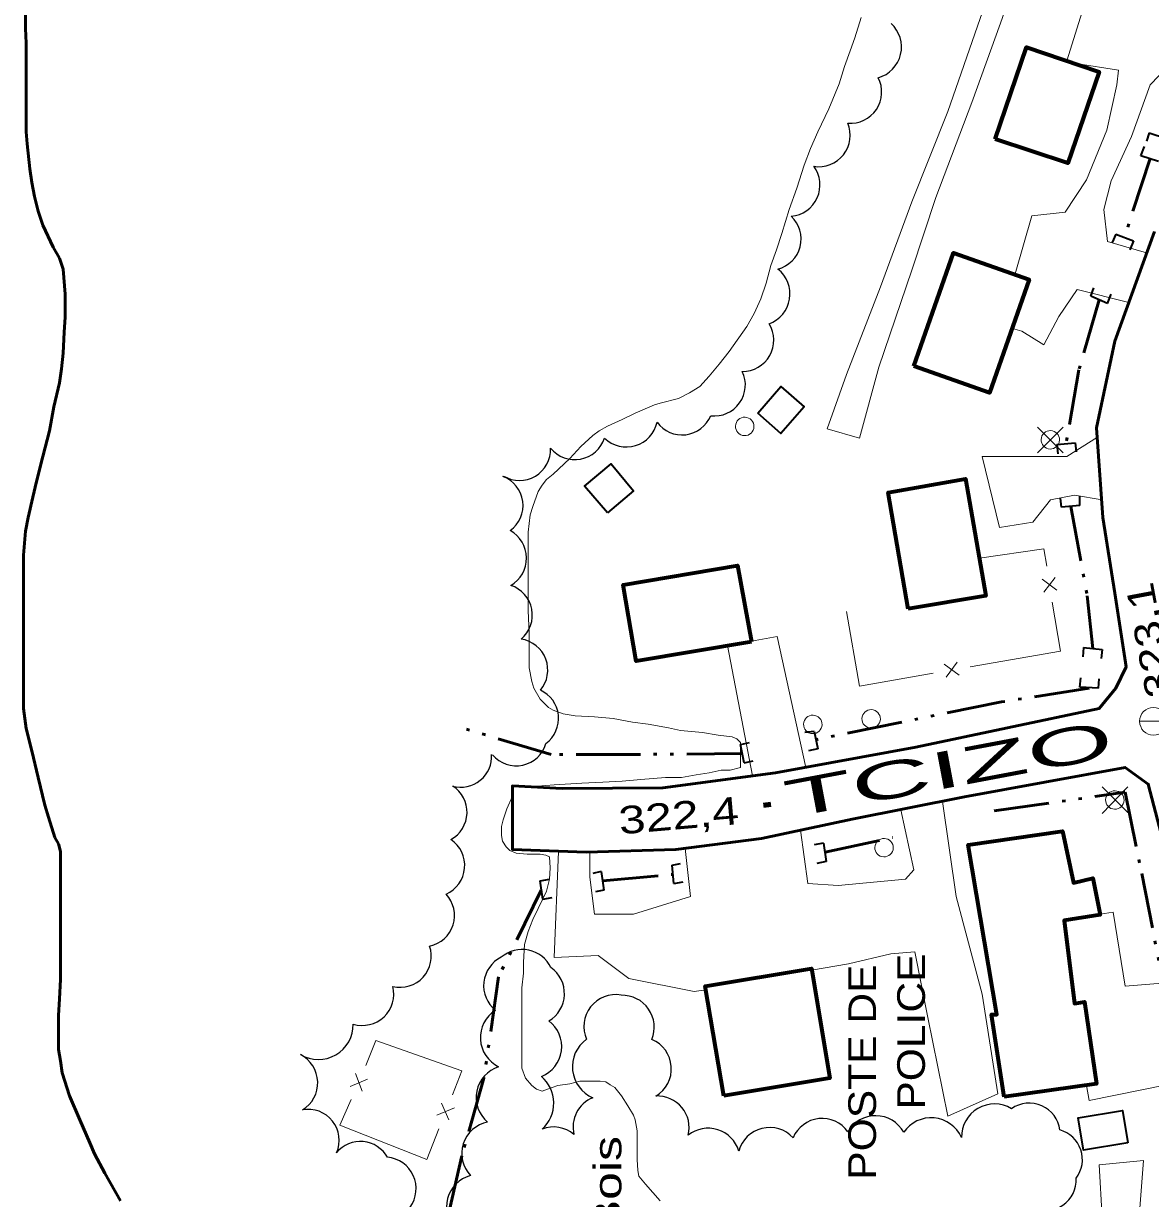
# Model space of a CAD drawing. Extents: x 240591 to 242335, y 5323482 to 5326937.
# Drawn here: x 240782 to 240904.2, y 5324661.9 to 5324789.3 of the extents above; entities that cross this region are included whole.
import ezdxf
from ezdxf.enums import TextEntityAlignment as Align

# ---------------------------------------------------------------- set-up
doc = ezdxf.new("R2010")
doc.units = 0
doc.header["$LTSCALE"] = 1.2
doc.linetypes.add('DASH_DOUBLE_DOT', pattern=[9.2, 5, -1.2, 0.3, -1.2, 0.3, -1.2])
doc.linetypes.add('LONG_DASHED', pattern=[7.5, 6, -1.5])
for name, color, linetype, lineweight in [('1', 7, 'Continuous', 53), ('19', 7, 'Continuous', 13), ('2', 7, 'Continuous', 13), ('21', 7, 'Continuous', 53), ('26', 7, 'Continuous', 35), ('3', 7, 'Continuous', 140), ('31', 7, 'Continuous', 70), ('36', 7, 'Continuous', 13), ('37', 7, 'Continuous', 13), ('4', 7, 'DASH_DOUBLE_DOT', 53), ('44', 7, 'Continuous', 25)]:
    doc.layers.add(name, color=color, linetype=linetype, lineweight=lineweight)

msp = doc.modelspace()

# ---------------------------------------------------------------- linework, layer by layer
at = {"layer": '1', "linetype": 'LONG_DASHED'}
msp.add_lwpolyline([(240792.5, 5324661.6), (240790.8, 5324664.6), (240789.7, 5324666.7), (240789.2, 5324667.9), (240788.1, 5324670.4), (240787, 5324673), (240786.2, 5324675.5), (240786, 5324676.8), (240785.8, 5324678), (240785.8, 5324679.1), (240785.8, 5324681.7), (240785.9, 5324683.5), (240786, 5324685.6), (240786, 5324688.1), (240786, 5324690.8), (240786, 5324693.6), (240786, 5324696.8), (240786, 5324699.5), (240785.8, 5324700.3), (240785.4, 5324701), (240784.7, 5324703.2), (240784.3, 5324704.5), (240783.6, 5324707.5), (240782.9, 5324710.4), (240782.3, 5324712.8), (240782, 5324715), (240782, 5324716.1), (240782, 5324719.8), (240782, 5324723.1), (240782, 5324726.3), (240782, 5324729.1), (240782, 5324731.6), (240782.2, 5324734.2), (240782.5, 5324735.7), (240783, 5324737.9), (240783.4, 5324739.6), (240784.1, 5324742.3), (240784.8, 5324745.1), (240785.3, 5324747.7), (240785.9, 5324750.3), (240786.1, 5324751.8), (240786.3, 5324753.5), (240786.4, 5324755.8), (240786.5, 5324757.4), (240786.5, 5324759.9), (240786.3, 5324762.6), (240785.9, 5324763.8), (240785.2, 5324765), (240784.1, 5324767.4), (240783.6, 5324768.9), (240783.2, 5324770.5), (240782.9, 5324772), (240782.7, 5324773.5), (240782.4, 5324776.2), (240782.3, 5324777.5), (240782.3, 5324779.8), (240782.3, 5324783.8), (240782.3, 5324787.1), (240782.2, 5324788.7), (240782.2, 5324791.6)], dxfattribs=at)
at = {"layer": '19'}
msp.add_line((240861, 5324707.7), (240858.3, 5324721.8), dxfattribs=at)
for points in [[(240905.5, 5324848.2), (240901.4, 5324836.4), (240898.2, 5324827.8), (240894.3, 5324814.9), (240890.3, 5324803), (240885.7, 5324789.8), (240882.2, 5324779.7), (240878.3, 5324769.9), (240874.9, 5324760.7), (240871.2, 5324751.2), (240869.1, 5324745.3), (240872.6, 5324744.3), (240874.7, 5324752), (240878.3, 5324762.5), (240880.9, 5324770.4), (240884.8, 5324780.7), (240887.9, 5324789.3), (240890.9, 5324797.9), (240894.2, 5324806.8), (240897.9, 5324817.2), (240900.9, 5324827.7), (240904.5, 5324836.1)], [(240895.1, 5324785.2), (240897.3, 5324792.3), (240902.9, 5324790.7), (240904.8, 5324794.1), (240907.1, 5324800.2), (240910.3, 5324809.3), (240903.8, 5324811.6), (240906, 5324817), (240912, 5324816), (240913.6, 5324817.7), (240916, 5324825.2), (240917.2, 5324831), (240909.6, 5324833.5)], [(240910.6, 5324783.9), (240907, 5324785.6), (240904.1, 5324782.6), (240902.1, 5324777), (240899.9, 5324772.2), (240899.1, 5324769.1), (240899.5, 5324765.6), (240902.6, 5324764.7), (240903.7, 5324764.4)], [(240889.5, 5324762.1), (240891.3, 5324768.4), (240894.9, 5324768.8), (240897.2, 5324772.3), (240899.4, 5324777.7), (240900.5, 5324782.6), (240900.7, 5324784.2), (240896.1, 5324784.9)], [(240901.8, 5324759), (240896.2, 5324760.4), (240894.2, 5324757.5), (240892.6, 5324754.4), (240890.2, 5324755.9), (240889.2, 5324756.2)], [(240898.4, 5324744.4), (240895.1, 5324742.3), (240885.9, 5324742.3), (240887.8, 5324734.6), (240891.4, 5324735.2), (240893.3, 5324737.6), (240895.9, 5324738.1), (240898.9, 5324737.6)], [(240860.9, 5324722.3), (240863.7, 5324722.8), (240866.8, 5324708.6)], [(240877.1, 5324704), (240878.5, 5324697.5), (240877.6, 5324696.5), (240870.3, 5324695.8), (240867, 5324696), (240866.2, 5324701.8)], [(240867.4, 5324686.6), (240871.4, 5324687.3), (240876, 5324688.4), (240878.6, 5324688.6), (240880, 5324681.5), (240882.2, 5324670.8), (240887.6, 5324673.2), (240885.9, 5324684), (240883.1, 5324694.6), (240881.6, 5324704.9)], [(240840, 5324699.5), (240839.5, 5324688), (240844.3, 5324688.2), (240847.6, 5324685.7), (240854.7, 5324684.3), (240856, 5324684.5)], [(240853.7, 5324699.8), (240854.3, 5324694.6), (240848.1, 5324692.7), (240843.9, 5324692.7), (240843.4, 5324696.7), (240843.4, 5324699.4)], [(240898.7, 5324692.7), (240900.1, 5324692.9), (240901.4, 5324684.9), (240905.4, 5324685.2), (240908.2, 5324685.9)], [(240910.4, 5324675), (240905.9, 5324674.2), (240897.5, 5324672.5), (240897.2, 5324674.1)], [(240898.3, 5324655.2), (240898.9, 5324659.8), (240898.6, 5324665.5), (240903.4, 5324666), (240902.9, 5324659.4), (240903.2, 5324656.4)]]:
    msp.add_lwpolyline(points, dxfattribs=at)
at = {"layer": '2'}
msp.add_line((240838.6, 5324699.1), (240838, 5324699.2), dxfattribs=at)
for points in [[(240854.4, 5324712.5), (240853.2, 5324712.6), (240851.9, 5324712.9), (240849.7, 5324713.3), (240848, 5324713.5), (240845.9, 5324713.9), (240843.9, 5324714.1), (240841.8, 5324714.2), (240840.5, 5324714.4), (240839.4, 5324714.8), (240838.9, 5324715.1), (240838, 5324716), (240837.3, 5324717.2), (240837.1, 5324717.9), (240836.8, 5324719.4), (240836.8, 5324720.3), (240836.8, 5324723.1), (240836.7, 5324725.6), (240836.7, 5324728.4), (240836.7, 5324731.2), (240836.7, 5324734.1), (240836.9, 5324736), (240837.2, 5324736.9), (240837.8, 5324738.5), (240838.2, 5324739.2), (240838.7, 5324739.8), (240839.4, 5324740.4), (240841.2, 5324742.1), (240842.4, 5324743.4), (240843.7, 5324744.6), (240844.4, 5324745.1), (240845.3, 5324745.6), (240846.9, 5324746.3), (240848.3, 5324747), (240850.4, 5324747.9), (240851, 5324748.1), (240853, 5324748.6), (240854.2, 5324749.2), (240855.3, 5324749.9), (240856.3, 5324751), (240857.4, 5324752.3), (240858.5, 5324753.7), (240860.4, 5324756.4), (240861.2, 5324757.8), (240861.9, 5324759.4), (240862.5, 5324761.1), (240863, 5324763), (240863.6, 5324764.7), (240864.2, 5324766.5), (240865, 5324769.1), (240865.8, 5324771.4), (240866.6, 5324773.9), (240867.3, 5324775.7), (240868.1, 5324777.5), (240869.3, 5324780), (240870.4, 5324782.7), (240871, 5324784.6), (240871.6, 5324786.3), (240872.1, 5324787.7), (240872.8, 5324789.9)], [(240836.8, 5324706.5), (240839.5, 5324706.7), (240842.5, 5324706.9), (240844.8, 5324707), (240846.9, 5324707.1), (240848.9, 5324707.3), (240851.6, 5324707.5), (240853.3, 5324707.5), (240854.9, 5324707.8), (240856.3, 5324708), (240857.6, 5324708.3), (240858.6, 5324708.3), (240859.7, 5324708.6), (240859.7, 5324709.2), (240859.7, 5324711.3), (240859.3, 5324711.7), (240858.8, 5324711.9), (240857.3, 5324712.1), (240855.6, 5324712.4), (240854.4, 5324712.5)], [(240838, 5324699.2), (240836.6, 5324699.2), (240835.4, 5324699.3), (240834.7, 5324699.6), (240834.3, 5324700), (240833.9, 5324700.6), (240833.8, 5324701.2), (240833.8, 5324702.2), (240834, 5324702.9), (240834.4, 5324704.1), (240835, 5324705.5)], [(240851, 5324661.6), (240849.4, 5324663.4), (240848.7, 5324664.3), (240848.6, 5324664.9), (240848.5, 5324666.1), (240848.5, 5324667.4), (240848.5, 5324669.2), (240848.3, 5324670.4), (240848.1, 5324670.9), (240847.5, 5324671.9), (240846.8, 5324673), (240846.1, 5324673.9), (240845.6, 5324674.2), (240845.1, 5324674.5), (240844.5, 5324674.6), (240843.9, 5324674.6), (240842.3, 5324674.6), (240841.2, 5324674.3), (240839.9, 5324674.1), (240839.3, 5324673.9), (240838.2, 5324673.5), (240837.6, 5324673.7), (240837.1, 5324674.1), (240836.4, 5324674.9), (240836, 5324676), (240836, 5324676.7), (240836, 5324679.6), (240836, 5324682.9), (240836, 5324684.7), (240836.2, 5324686.3), (240836.2, 5324687.5), (240836.3, 5324689.4), (240836.7, 5324690.8), (240837.2, 5324692.1), (240837.8, 5324693.3), (240838.7, 5324695.2), (240839, 5324696.5), (240839.1, 5324697.7), (240839, 5324698.9), (240838.6, 5324699.1)]]:
    msp.add_lwpolyline(points, dxfattribs=at)
at = {"layer": '21'}
msp.add_lwpolyline([(240904.6, 5324766.7), (240900.3, 5324754.8), (240898.3, 5324745.4), (240899, 5324735.7), (240900.3, 5324727.5), (240901.5, 5324719.5), (240900.4, 5324717.2), (240898.6, 5324715), (240878.7, 5324710.8), (240863.5, 5324708), (240851.3, 5324706.4), (240840.4, 5324706.3), (240835, 5324706.6), (240835, 5324699.7), (240843, 5324699.4), (240852.7, 5324699.7), (240862, 5324700.9), (240871.8, 5324703), (240884, 5324705.4), (240901.4, 5324708.6), (240903.9, 5324706.8), (240905.3, 5324701.4)], dxfattribs=at)
at = {"layer": '26'}
for p, q in [((240904, 5324777.4), (240903.7, 5324776.5)), ((240904, 5324777.4), (240905.9, 5324776.8)), ((240903.1, 5324774.9), (240903.5, 5324775.9)), ((240905, 5324774.3), (240903.1, 5324774.9)), ((240900.4, 5324766.4), (240900, 5324765.5)), ((240900.4, 5324766.4), (240902.3, 5324765.7)), ((240902.3, 5324765.7), (240901.9, 5324764.7)), ((240897.7, 5324759.7), (240898, 5324760.6)), ((240899.5, 5324758.9), (240897.7, 5324759.7)), ((240899.5, 5324758.9), (240899.9, 5324759.9)), ((240894, 5324743.6), (240896, 5324743.8)), ((240894, 5324743.6), (240894.1, 5324742.6)), ((240896, 5324743.8), (240896.1, 5324742.8)), ((240894.5, 5324736.8), (240894.4, 5324737.8)), ((240896.5, 5324737), (240894.5, 5324736.8)), ((240896.5, 5324737), (240896.5, 5324738)), ((240896.9, 5324721.6), (240896.8, 5324720.6)), ((240896.9, 5324721.6), (240898.9, 5324721.4)), ((240898.9, 5324721.4), (240898.8, 5324720.4)), ((240896.5, 5324717.3), (240896.6, 5324718.3)), ((240898.5, 5324717.2), (240898.6, 5324718.2)), ((240898.5, 5324717.2), (240896.5, 5324717.3)), ((240859.7, 5324711.1), (240860.7, 5324711.3)), ((240867.7, 5324712.5), (240866.7, 5324712.4)), ((240867.7, 5324712.5), (240868.1, 5324710.6)), ((240860.1, 5324709.1), (240859.7, 5324711.1)), ((240868.1, 5324710.6), (240867.1, 5324710.4)), ((240860.1, 5324709.1), (240861.1, 5324709.3)), ((240868.7, 5324700.4), (240867.7, 5324700.2)), ((240868.7, 5324700.4), (240869, 5324698.4)), ((240844.6, 5324697.3), (240843.7, 5324697.1)), ((240844.6, 5324697.3), (240844.9, 5324695.3)), ((240852.3, 5324698), (240853.2, 5324698.2)), ((240852.5, 5324696), (240852.3, 5324698)), ((240869, 5324698.4), (240868, 5324698.2)), ((240838, 5324696.3), (240839, 5324696.5)), ((240838.3, 5324694.3), (240838, 5324696.3)), ((240852.5, 5324696), (240853.5, 5324696.2)), ((240844.9, 5324695.3), (240844, 5324695.1)), ((240838.3, 5324694.3), (240839.3, 5324694.5))]:
    msp.add_line(p, q, dxfattribs=at)
at = {"layer": '3'}
msp.add_line((240862.2, 5324704.5), (240863, 5324704.6), dxfattribs=at)
at = {"layer": '31'}
for points in [[(240887.3, 5324776.7), (240890.7, 5324786.7), (240898.6, 5324784), (240895.2, 5324774.1)], [(240878.5, 5324752.1), (240882.8, 5324764.4), (240891, 5324761.5), (240886.7, 5324749.2)], [(240877.9, 5324725.8), (240875.7, 5324738.4), (240884.1, 5324739.9), (240886.3, 5324727.2)], [(240860.9, 5324722.2), (240848.4, 5324720.1), (240847, 5324728.4), (240859.4, 5324730.5)], [(240888.3, 5324672.9), (240886.9, 5324681.8), (240887.5, 5324681.8), (240884.4, 5324700.2), (240894.6, 5324701.7), (240895.8, 5324696.1), (240897.9, 5324696.6), (240898.7, 5324692.6), (240894.8, 5324692), (240895.9, 5324683), (240897, 5324683.2), (240898.3, 5324674.3)], [(240857.9, 5324673), (240855.9, 5324684.9), (240867.4, 5324686.8), (240869.4, 5324674.9)]]:
    msp.add_lwpolyline(points, close=True, dxfattribs=at)
at = {"layer": '31', "lineweight": 35}
for points in [[(240861.6, 5324747), (240864.1, 5324749.9), (240866.6, 5324747.7), (240864.1, 5324744.8)], [(240845.3, 5324736.2), (240842.8, 5324739.1), (240845.7, 5324741.5), (240848.1, 5324738.6)], [(240901.7, 5324667.9), (240896.9, 5324667.1), (240896.3, 5324670.6), (240901.1, 5324671.4)]]:
    msp.add_lwpolyline(points, close=True, dxfattribs=at)
at = {"layer": '36'}
for p, q in [((240891.9, 5324742.7), (240894.7, 5324745.5)), ((240894.7, 5324742.7), (240891.9, 5324745.5)), ((240903, 5324713.6), (240906, 5324713.6)), ((240898.9, 5324703.6), (240901.7, 5324706.5)), ((240901.7, 5324703.7), (240898.9, 5324706.5))]:
    msp.add_line(p, q, dxfattribs=at)
msp.add_circle((240904.469, 5324713.602), 1.5, dxfattribs=at)
for centre in [(240860.173, 5324745.57), (240893.295, 5324744.118), (240867.553, 5324713.26), (240873.87, 5324713.863), (240900.285, 5324705.068), (240875.273, 5324699.9)]:
    msp.add_ellipse(centre, major_axis=(0.23, 0.973), ratio=0.999999, dxfattribs=at)
at = {"layer": '37'}
for p, q in [((240892.6, 5324727.6), (240893.8, 5324729.2)), ((240892.4, 5324729), (240894, 5324727.8)), ((240893.5, 5324726.5), (240894.4, 5324721.2)), ((240884.6, 5324719.5), (240894.4, 5324721.2)), ((240883.4, 5324718.6), (240881.8, 5324719.8)), ((240882, 5324718.4), (240883.2, 5324720)), ((240828.5, 5324673.1), (240829.5, 5324675.7)), ((240819.3, 5324674.8), (240817.4, 5324674)), ((240818.7, 5324673.5), (240818, 5324675.4)), ((240828.1, 5324670.4), (240827.3, 5324672.2)), ((240828.7, 5324671.7), (240826.8, 5324670.9)), ((240825.7, 5324666.1), (240827, 5324669.4))]:
    msp.add_line(p, q, dxfattribs=at)
for points in [[(240885.6, 5324731.3), (240892.6, 5324732.3), (240892.9, 5324730.4)], [(240871.2, 5324725.5), (240872.6, 5324717.4), (240880.6, 5324718.8)], [(240819.1, 5324676.3), (240820.2, 5324679), (240829.5, 5324675.7)], [(240825.7, 5324666.1), (240816.3, 5324669.8), (240817.5, 5324672.6)]]:
    msp.add_lwpolyline(points, dxfattribs=at)
at = {"layer": '4'}
for p, q in [((240904.1, 5324774.6), (240901.3, 5324766)), ((240868.9, 5324699.4), (240876.2, 5324701)), ((240844.8, 5324696.3), (240852.4, 5324697))]:
    msp.add_line(p, q, dxfattribs=at)
for points in [[(240898.6, 5324759.3), (240896.4, 5324751.7), (240895, 5324743.7)], [(240895.5, 5324736.9), (240897.3, 5324727.2), (240897.9, 5324721.5)], [(240897.5, 5324717.2), (240888, 5324715.7), (240867.9, 5324711.6)], [(240859.9, 5324710.1), (240847.9, 5324710), (240839.2, 5324710), (240829.8, 5324712.8)], [(240887.2, 5324703.9), (240901.4, 5324705.9), (240903.2, 5324697.1), (240905.2, 5324686.9)], [(240838.1, 5324695.3), (240833.5, 5324685.9), (240831.9, 5324674.9), (240829.5, 5324666.5), (240827.5, 5324657.6), (240828.4, 5324652.8), (240831.5, 5324648.6), (240834.1, 5324645.5), (240836.6, 5324641.3)]]:
    msp.add_lwpolyline(points, dxfattribs=at)
at = {"layer": '44'}
for centre, radius, start, end in [((240833.763, 5324725.107), 3.389, 309.9783, 71.99716), ((240825.341, 5324692.537), 3.376, 281.60636, 43.24494), ((240822.808, 5324688.147), 3.39, 256.55959, 18.63312), ((240818.745, 5324684.006), 3.382, 252.53464, 14.45049), ((240836.874, 5324678.327), 3.466, 291.42236, 53.41332), ((240834.562, 5324672.819), 3.499, 107.8428, 229.72104)]:
    msp.add_arc(centre, radius, start, end, dxfattribs=at)
for centre, major_axis, ratio, start_param, end_param in [((240873.706, 5324786.699), (-2.534, 2.353), 0.999984, 2.5927844, 4.7198274), ((240871.626, 5324781.825), (2.292, -2.494), 0.999926, 5.4555318, 7.5844349), ((240868.186, 5324777.142), (2.462, -2.367), 0.999589, 5.3203403, 7.4421118), ((240864.926, 5324771.736), (3.106, -1.382), 0.999909, 5.2177093, 7.3433293), ((240862.899, 5324765.89), (3.282, -0.825), 0.999035, 5.2157192, 7.3444173), ((240861.636, 5324759.919), (3.395, -0.535), 0.999728, 5.2173431, 7.343939), ((240859.926, 5324754.916), (2.955, -1.653), 0.999909, 5.2173756, 7.3447269), ((240856.874, 5324750.068), (1.978, 2.729), 0.998702, 3.652309, 5.787764), ((240847.345, 5324746.748), (2.311, 2.499), 0.999994, 3.1199124, 5.2431782), ((240853.379, 5324748.003), (3.325, 0.472), 0.999857, 3.6325909, 5.750236), ((240835.773, 5324743.071), (0.027, 3.365), 0.998254, 2.6059686, 4.7588404), ((240841.749, 5324745.379), (0.296, -3.395), 0.999588, 5.3190091, 7.4448944), ((240832.776, 5324737.003), (-0.437, 3.338), 0.99898, 3.6349046, 5.7898733), ((240833.115, 5324731.28), (3.405, 0.039), 0.999044, 5.2219293, 7.345087), ((240835.44, 5324719.162), (-3.344, 0.53), 0.999983, 2.5945536, 4.7213653), ((240836.635, 5324713.915), (-2.787, 1.881), 0.99766, 2.7990146, 4.880226), ((240835.404, 5324712.129), (-0.56, -3.313), 0.998198, 5.5851245, 7.743734), ((240829.375, 5324709.815), (2.867, 1.775), 0.999212, 3.8999153, 5.7863309), ((240826.709, 5324703.737), (0.632, 3.305), 0.999082, 3.8337816, 5.9025778), ((240826.394, 5324697.969), (3.416, -0.294), 0.997038, 5.2203752, 7.3395329), ((240836.052, 5324685.417), (-3.401, 0.562), 0.99994, 3.7489922, 5.5939285), ((240835.32, 5324684.941), (-0.642, -3.39), 0.998768, 3.7928627, 5.7892241), ((240837.178, 5324684.083), (-0.142, 3.454), 0.99877, 3.6360112, 5.6267527), ((240846.191, 5324680.514), (-2.122, -2.727), 0.998769, 3.6362881, 5.7884898), ((240846.9, 5324680.443), (-2.175, 2.689), 0.999027, 3.6369335, 5.6344032), ((240835.034, 5324679.301), (-3.513, -0.224), 0.995538, 5.2136237, 7.3363941), ((240813.952, 5324680.708), (0.744, -3.705), 0.999968, 5.5483508, 7.6749955), ((240845.129, 5324676.146), (-3.619, -0.398), 0.999822, 5.217384, 7.3471787), ((240848.775, 5324675.922), (-0.346, 3.433), 0.998775, 3.5787133, 5.7909417), ((240810.458, 5324674.404), (3.432, -0.127), 0.999261, 5.2948405, 7.4187204), ((240835.613, 5324672.193), (3.767, -0.806), 0.99996, 5.6703074, 7.349067), ((240845.005, 5324669.59), (2.531, -2.346), 0.996486, 2.6986453, 4.1214336), ((240850.699, 5324669.529), (-1.843, 2.919), 0.999257, 3.911851, 5.7663993), ((240887.241, 5324668.526), (-1.576, 3.219), 0.999199, 5.288545, 7.4145007), ((240890.975, 5324668.87), (-3.15, -1.195), 0.985836, 2.9011879, 4.9533692), ((240812.86, 5324668.168), (-2.108, 2.618), 0.999426, 3.6237269, 5.7906925), ((240868.567, 5324667.079), (-0.422, 3.438), 0.99161, 5.2106509, 7.325786), ((240874.365, 5324667.339), (0.056, 3.5), 0.991555, 5.2354727, 7.3460222), ((240880.372, 5324667.02), (0.33, 3.58), 0.999494, 5.2193565, 7.349168), ((240832.987, 5324666.727), (-3.327, 1.06), 0.999463, 5.2186746, 7.3451127), ((240839.438, 5324666.172), (-3.37, 0.729), 0.999757, 4.2256404, 5.2866928), ((240856.209, 5324666.03), (-3.381, 0.702), 0.99994, 3.6340022, 5.5933767), ((240862.866, 5324666.088), (-0.384, 3.45), 0.999766, 5.3499278, 7.4745315), ((240893.404, 5324666.081), (-3.314, 0.588), 0.996075, 2.6730141, 4.6147146), ((240818.519, 5324664.681), (-3.34, 0.403), 0.999936, 3.7733395, 5.7104787), ((240821.14, 5324662.926), (2.651, 2.155), 0.999159, 4.9761344, 7.0809743), ((240831.319, 5324660.985), (-3.359, 0.866), 0.999995, 5.2210176, 7.3467234), ((240892.725, 5324663.873), (3.31, 0.64), 0.992679, 4.1123932, 6.1500355)]:
    msp.add_ellipse(centre, major_axis=major_axis, ratio=ratio, start_param=start_param, end_param=end_param, dxfattribs=at)

# ---------------------------------------------------------------- texts
at = {"layer": '21', "width": 2.25}
msp.add_text('TCIZO', height=4, rotation=10.699, dxfattribs=at).set_placement((240864.9, 5324703.1))
at = {"layer": '3', "width": 1.25}
msp.add_text('323,1', height=3, rotation=100.654, dxfattribs=at).set_placement((240906.7, 5324716.5))
at = {"layer": '3', "width": 1.3}
msp.add_text('322,4', height=3, rotation=4.925, dxfattribs=at).set_placement((240859.642, 5324702.458), align=Align.RIGHT)
at = {"layer": '31', "width": 1.15}
for s, p in [('POLICE', (240879.7, 5324671.5)), ('POSTE DE', (240874.4, 5324663.9))]:
    msp.add_text(s, height=3, rotation=90, dxfattribs=at).set_placement(p)
at = {"layer": '44', "width": 1.35}
msp.add_text('Bois', height=3, rotation=90, dxfattribs=at).set_placement((240846.8, 5324658.1))

doc.saveas('drawing.dxf')
